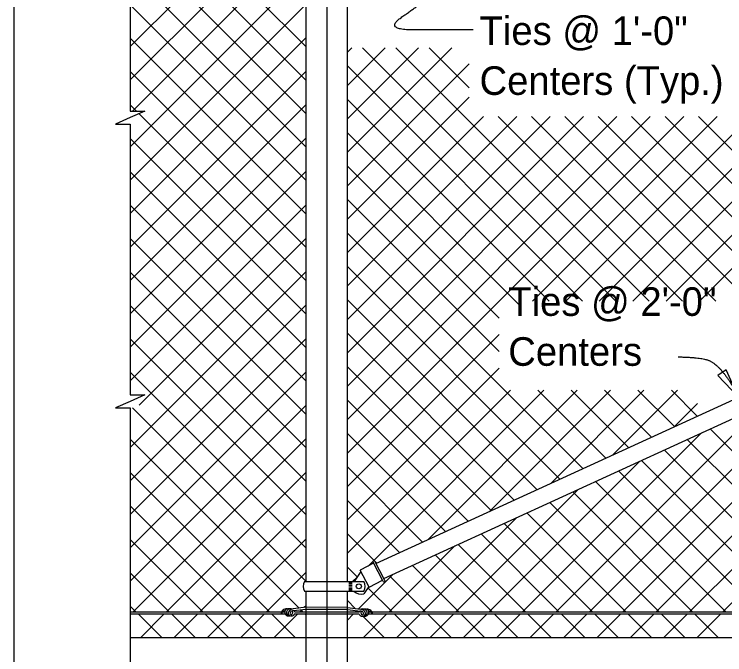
# Model space of a CAD drawing. Extents: x 0 to 41.1, y 0 to 26.4.
# Drawn here: x 0 to 5.02, y 17.35 to 21.87 of the extents above; entities that cross this region are included whole.
import ezdxf

# ---------------------------------------------------------------- set-up
doc = ezdxf.new("R2010")
doc.units = 0
for name, color, linetype in [('CL_Major', 7, 'Continuous'), ('Dimension', 7, 'Continuous'), ('Miscellaneous', 7, 'Continuous'), ('Miscellaneous1', 7, 'Continuous'), ('SteelMisc', 7, 'Continuous'), ('SteelMisc_h', 7, 'Continuous'), ('SupstrConc', 7, 'Continuous'), ('TextStructures', 7, 'Continuous')]:
    doc.layers.add(name, color=color, linetype=linetype)

msp = doc.modelspace()

# ---------------------------------------------------------------- linework, layer by layer
at = {"layer": 'CL_Major'}
msp.add_line((2.2062, 25.6784), (2.2062, 14.8533), dxfattribs=at)
at = {"layer": 'Dimension'}
for points in [[(0.8194, 24.349), (0.8194, 21.1819), (0.9227, 21.1819), (0.8194, 21.1369), (0.716, 21.0919), (0.8194, 21.0919), (0.8194, 20.1983)], [(0.8194, 20.1983), (0.8194, 19.1806), (0.9227, 19.1806), (0.8194, 19.1356), (0.716, 19.0906), (0.8194, 19.0906), (0.8194, 16.8862)]]:
    msp.add_lwpolyline(points, dxfattribs=at)
msp.add_lwpolyline([(5.1135, 19.1655), (5.0266, 19.358), (4.968, 19.3186)], close=True, dxfattribs=at)
for points in [[(3.2402, 21.7554), (3.0279, 21.7554), (2.6079, 21.7554), (2.8581, 21.9325), (2.9953, 22.0352), (2.7847, 22.0777), (2.352, 22.06)], [(4.6876, 19.4494), (4.8459, 19.4462), (4.9517, 19.4061), (5.0648, 19.263), (5.1136, 19.1655)]]:
    msp.add_open_spline(points, degree=2, dxfattribs=at)
at = {"layer": 'Miscellaneous'}
for p, q in [((1.8028, 22.3863), (0.8192, 21.4028)), ((1.567, 22.3862), (0.8192, 21.6385)), ((2.0603, 21.1639), (0.8381, 22.3861)), ((2.0603, 21.3996), (1.0738, 22.3862)), ((2.0603, 21.6353), (1.3094, 22.3862)), ((6.6782, 22.39), (4.1304, 19.8423)), ((6.9139, 22.39), (4.3661, 19.8423)), ((7.1496, 22.39), (4.6018, 19.8423)), ((7.3853, 22.39), (4.8375, 19.8423)), ((2.0163, 22.3642), (0.8341, 21.1819)), ((2.0603, 22.1725), (0.8192, 20.9314)), ((2.0603, 20.9282), (0.8192, 22.1693)), ((2.0603, 21.9368), (0.8192, 20.6957)), ((2.0603, 20.6925), (0.8192, 21.9336)), ((2.0603, 21.701), (0.8192, 20.46)), ((2.0603, 20.4568), (0.8192, 21.6979)), ((2.6187, 21.6304), (2.352, 21.3636)), ((2.383, 21.6304), (2.352, 21.5993)), ((2.8544, 21.6304), (2.352, 21.1279)), ((3.0901, 21.6304), (2.352, 20.8922)), ((4.2468, 19.8423), (2.4587, 21.6304)), ((4.4825, 19.8423), (2.6944, 21.6304)), ((3.2122, 21.3482), (2.9301, 21.6304)), ((3.2122, 21.5167), (2.352, 20.6565)), ((4.011, 19.8423), (2.352, 21.5013)), ((2.0603, 21.4653), (0.8192, 20.2243)), ((2.0603, 20.2211), (0.8192, 21.4622)), ((3.2122, 21.281), (2.352, 20.4208)), ((2.0603, 21.2296), (0.8192, 19.9886)), ((0.8638, 21.1819), (0.8192, 21.2265)), ((3.7753, 19.8423), (2.352, 21.2656)), ((2.0603, 19.9854), (0.8817, 21.164)), ((4.2544, 21.1447), (2.352, 19.2423)), ((3.783, 21.1447), (2.352, 19.7137)), ((3.3116, 21.1447), (2.352, 20.1851)), ((3.5473, 21.1447), (2.352, 19.9494)), ((4.0187, 21.1447), (2.352, 19.478)), ((4.4901, 21.1447), (2.352, 19.0066)), ((4.7182, 19.8423), (3.4157, 21.1447)), ((4.7258, 21.1447), (3.4233, 19.8423)), ((4.9539, 19.8423), (3.6514, 21.1447)), ((4.9615, 21.1447), (3.659, 19.8423)), ((5.1896, 19.8423), (3.8871, 21.1447)), ((5.1972, 21.1447), (3.8947, 19.8423)), ((5.4253, 19.8423), (4.1228, 21.1447)), ((5.9529, 19.5503), (4.3585, 21.1447)), ((6.1145, 19.6244), (4.5942, 21.1447)), ((6.2762, 19.6985), (4.8299, 21.1447)), ((3.5642, 19.8177), (2.352, 21.0299)), ((2.0603, 20.9939), (0.8192, 19.7529)), ((2.0603, 19.7497), (0.8192, 20.9908)), ((3.4233, 19.7229), (2.352, 20.7942)), ((2.0603, 20.7582), (0.8192, 19.5171)), ((2.0603, 19.514), (0.8192, 20.7551)), ((2.0603, 20.5225), (0.8192, 19.2814)), ((2.0603, 19.2783), (0.8192, 20.5194)), ((3.4233, 19.4872), (2.352, 20.5585)), ((4.0136, 18.6612), (2.352, 20.3228)), ((2.0603, 19.0426), (0.8192, 20.2837)), ((2.0603, 20.2868), (0.8817, 19.1083)), ((3.852, 18.5871), (2.352, 20.0871)), ((7.463, 20.1106), (5.0009, 17.6486)), ((2.0603, 20.0511), (0.8192, 18.81)), ((2.0603, 18.8069), (0.8192, 20.048)), ((7.0277, 19.9111), (4.7652, 17.6486)), ((2.0603, 19.8154), (0.8192, 18.5743)), ((3.6903, 18.513), (2.352, 19.8514)), ((3.4233, 19.8423), (2.352, 18.7709)), ((2.0603, 18.5712), (0.8192, 19.8123)), ((6.5925, 19.7116), (4.5295, 17.6486)), ((3.5287, 18.439), (2.352, 19.6157)), ((2.0603, 19.5797), (0.8192, 18.3386)), ((2.0603, 18.3355), (0.8192, 19.5766)), ((3.4233, 19.6066), (2.352, 18.5352)), ((6.1573, 19.5121), (4.2938, 17.6486)), ((3.3671, 18.3649), (2.352, 19.38)), ((3.4233, 19.3709), (2.352, 18.2995)), ((2.0603, 19.344), (0.8192, 18.1029)), ((2.0603, 18.0998), (0.8192, 19.3409)), ((5.7221, 19.3126), (4.0581, 17.6486)), ((3.5027, 19.2146), (2.352, 18.0638)), ((3.7384, 19.2146), (2.4979, 17.974)), ((3.9741, 19.2146), (2.919, 18.1595)), ((4.2098, 19.2146), (3.3543, 18.359)), ((4.1752, 18.7353), (3.6959, 19.2146)), ((4.4455, 19.2146), (3.7895, 18.5585)), ((4.3368, 18.8094), (3.9317, 19.2146)), ((4.4984, 18.8835), (4.1674, 19.2146)), ((4.6812, 19.2146), (4.2247, 18.758)), ((4.66, 18.9576), (4.4031, 19.2146)), ((4.8216, 19.0317), (4.6388, 19.2146)), ((3.2055, 18.2908), (2.352, 19.1443)), ((5.2869, 19.1131), (3.8224, 17.6486)), ((4.8227, 19.1203), (4.6599, 18.9575)), ((2.0603, 19.1083), (0.8192, 17.8672)), ((2.0603, 17.8641), (0.8339, 19.0905)), ((4.8517, 18.9136), (3.5867, 17.6486)), ((6.2048, 17.6486), (4.912, 18.9413)), ((2.012, 17.6767), (0.8192, 18.8695)), ((2.0603, 18.8726), (0.8363, 17.6486)), ((3.0439, 18.2167), (2.352, 18.9086)), ((5.9691, 17.6486), (4.7504, 18.8672)), ((5.7333, 17.6486), (4.5888, 18.7931)), ((4.4165, 18.7141), (3.3509, 17.6486)), ((5.4976, 17.6486), (4.4272, 18.719)), ((2.8823, 18.1426), (2.352, 18.6729)), ((1.8044, 17.6486), (0.8192, 18.6338)), ((2.0603, 18.6369), (1.072, 17.6486)), ((5.2619, 17.6486), (4.2656, 18.6449)), ((5.0262, 17.6486), (4.104, 18.5708)), ((3.9813, 18.5146), (3.1152, 17.6486)), ((4.7905, 17.6486), (3.9424, 18.4967)), ((2.7207, 18.0685), (2.352, 18.4372)), ((4.5548, 17.6486), (3.7807, 18.4227)), ((1.5687, 17.6486), (0.8192, 18.3981)), ((2.0603, 18.4012), (1.3077, 17.6486)), ((3.5461, 18.3151), (2.8795, 17.6486)), ((4.3191, 17.6486), (3.6191, 18.3486)), ((4.0834, 17.6486), (3.4575, 18.2745)), ((1.333, 17.6486), (0.8192, 18.1624)), ((2.0603, 18.1655), (1.5434, 17.6486)), ((2.5591, 17.9944), (2.352, 18.2015)), ((3.8477, 17.6486), (3.2959, 18.2004)), ((3.1108, 18.1156), (2.6438, 17.6486)), ((3.612, 17.6486), (3.1343, 18.1263)), ((3.3763, 17.6486), (2.9727, 18.0522)), ((2.4208, 17.897), (2.352, 17.9658)), ((3.1406, 17.6486), (2.8111, 17.9781)), ((1.0973, 17.6486), (0.8192, 17.9267)), ((2.0603, 17.9298), (1.7791, 17.6486)), ((2.6756, 17.9161), (2.4309, 17.6713)), ((2.4207, 17.8968), (2.3885, 17.8646)), ((2.9049, 17.6486), (2.6494, 17.904)), ((2.6692, 17.6486), (2.4966, 17.8212)), ((2.4079, 17.6742), (2.352, 17.7301)), ((0.8616, 17.6486), (0.8192, 17.691)), ((2.0315, 17.6653), (2.0148, 17.6486)), ((2.0401, 17.6486), (2.0242, 17.6645)), ((2.0603, 17.6941), (2.0474, 17.6812)), ((2.4193, 17.6597), (2.4081, 17.6486)), ((2.4335, 17.6486), (2.4228, 17.6593)), ((0.8215, 17.6338), (0.8192, 17.6315)), ((1.0409, 17.4693), (0.8764, 17.6338)), ((1.0572, 17.6338), (0.8927, 17.4693)), ((1.2766, 17.4693), (1.1121, 17.6338)), ((1.2929, 17.6338), (1.1284, 17.4693)), ((1.5123, 17.4693), (1.3478, 17.6338)), ((1.5286, 17.6338), (1.3641, 17.4693)), ((1.748, 17.4693), (1.5835, 17.6338)), ((1.7643, 17.6338), (1.5998, 17.4693)), ((1.9837, 17.4693), (1.8192, 17.6338)), ((2, 17.6338), (1.8355, 17.4693)), ((2.0603, 17.6284), (2.0549, 17.6338)), ((2.3934, 17.6338), (2.352, 17.5924)), ((2.6127, 17.4693), (2.4617, 17.6203)), ((2.6291, 17.6338), (2.4646, 17.4693)), ((2.8484, 17.4693), (2.684, 17.6338)), ((2.8648, 17.6338), (2.7003, 17.4693)), ((3.0842, 17.4693), (2.9197, 17.6338)), ((3.1005, 17.6338), (2.936, 17.4693)), ((3.3199, 17.4693), (3.1554, 17.6338)), ((3.3362, 17.6338), (3.1717, 17.4693)), ((3.5556, 17.4693), (3.3911, 17.6338)), ((3.5719, 17.6338), (3.4074, 17.4693)), ((3.7913, 17.4693), (3.6268, 17.6338)), ((3.8076, 17.6338), (3.6431, 17.4693)), ((4.027, 17.4693), (3.8625, 17.6338)), ((4.0433, 17.6338), (3.8788, 17.4693)), ((4.2627, 17.4693), (4.0982, 17.6338)), ((4.279, 17.6338), (4.1145, 17.4693)), ((4.4984, 17.4693), (4.3339, 17.6338)), ((4.5147, 17.6338), (4.3502, 17.4693)), ((4.7341, 17.4693), (4.5696, 17.6338)), ((4.7504, 17.6338), (4.5859, 17.4693)), ((4.9698, 17.4693), (4.8053, 17.6338)), ((4.9861, 17.6338), (4.8216, 17.4693))]:
    msp.add_line(p, q, dxfattribs=at)
at = {"layer": 'Miscellaneous1'}
msp.add_lwpolyline([(0, 26.4), (41.0667, 26.4), (41.0667, 0), (0, 0)], close=True, dxfattribs=at)
at = {"layer": 'SteelMisc'}
for p, q in [((2.0603, 17.8646), (2.0603, 24.349)), ((2.352, 17.8646), (2.352, 24.349)), ((2.5526, 17.9915), (11.8021, 22.2317)), ((2.6096, 17.8858), (11.8582, 22.1255)), ((2.6171, 17.8717), (2.5446, 18.0088)), ((2.5369, 17.9947), (2.4426, 17.9448)), ((2.6052, 17.8654), (2.5328, 18.0026)), ((2.4468, 17.9368), (2.3999, 17.8651)), ((2.5063, 17.8242), (2.4426, 17.9448)), ((2.049, 17.8646), (2.4687, 17.8646)), ((2.3864, 17.8584), (2.3629, 17.8584)), ((2.5063, 17.8242), (2.6006, 17.8741)), ((2.3864, 17.8486), (2.3629, 17.8486)), ((2.3864, 17.8368), (2.3629, 17.8368)), ((2.3864, 17.825), (2.3629, 17.825)), ((2.3864, 17.8142), (2.3629, 17.8142)), ((2.5029, 17.8308), (2.4681, 17.7777)), ((2.0491, 17.7968), (2.4687, 17.7968)), ((2.0603, 17.0944), (2.0603, 17.7968)), ((2.352, 17.0944), (2.352, 17.7968)), ((2.3864, 17.8046), (2.3629, 17.8046)), ((2.0608, 17.6829), (1.9689, 17.6713)), ((2.0608, 17.6683), (1.9689, 17.6588)), ((2.352, 17.6812), (2.0608, 17.6829)), ((2.352, 17.6667), (2.0608, 17.6683)), ((2.352, 17.6812), (2.4449, 17.6695)), ((2.352, 17.6667), (2.4448, 17.657)), ((1.8859, 17.6486), (0.8192, 17.6486)), ((1.9145, 17.6338), (0.8192, 17.6338)), ((1.9096, 17.6486), (1.8943, 17.6486)), ((2.0603, 17.6338), (1.9773, 17.6338)), ((2.0603, 17.6486), (1.9799, 17.6486)), ((2.4342, 17.6486), (2.352, 17.6486)), ((2.4356, 17.6338), (2.352, 17.6338)), ((11.8982, 17.6338), (2.5005, 17.6338)), ((2.5172, 17.6486), (2.5041, 17.6486)), ((11.8969, 17.6486), (2.5271, 17.6486))]:
    msp.add_line(p, q, dxfattribs=at)
for centre, start, end in [((2.5385, 18.0058), 27.851, 207.851), ((2.611, 17.8686), 207.851, 27.851)]:
    msp.add_arc(centre, 0.00673, start, end, dxfattribs=at)
for centre, major_axis, ratio, start_param, end_param in [((2.1181, 17.8309), (-0.0776, 0), 0.957868, 5.811591, 6.758603), ((2.3995, 17.8309), (0.0776, 0), 0.957868, 5.810211, 6.75616), ((2.4515, 17.846), (-0.0647, -0.0342), 0.957868, 0.271397, 1.331255), ((1.9209, 17.6361), (0.0373, 0), 0.957868, 1.427863, 3.108042), ((1.942, 17.5964), (-0.0724, 0), 0.957868, 5.133134, 5.652106), ((1.9345, 17.648), (-0.0249, 0), 0.957868, 5.913851, 7.104804), ((1.9333, 17.6505), (0.023, 0), 0.957868, 1.234085, 2.861055), ((1.9521, 17.6452), (0.0295, 0), 0.957868, 1.132635, 3.996184), ((1.9656, 17.647), (-0.0303, -0.0108), 0.724765, 4.35367, 6.224248), ((1.9706, 17.634), (-0.0259, 0), 0.957868, 4.777514, 5.646371), ((1.9549, 17.6463), (0.0119, 0), 0.957868, 5.725876, 7.416677), ((1.9551, 17.6451), (0.0251, 0), 0.957868, 0.146361, 0.642491), ((2.4586, 17.6433), (-0.0251, 0), 0.957868, 5.640601, 6.061443), ((2.4431, 17.6323), (0.0259, 0), 0.957868, 0.636815, 1.505671), ((2.4482, 17.6452), (0.0303, -0.0108), 0.724765, 0.058937, 1.929515), ((2.4617, 17.6434), (-0.0295, 0), 0.957868, 2.287002, 5.15055), ((2.4804, 17.6488), (-0.023, 0), 0.957868, 3.422131, 5.0491), ((2.4929, 17.6343), (-0.0373, 0), 0.957868, 3.175144, 4.855322), ((2.4718, 17.5946), (0.0724, 0), 0.957868, 0.631079, 1.150052), ((1.9359, 17.644), (0.0231, 0), 0.957868, 3.795406, 4.839145), ((1.942, 17.6383), (0.0206, -0.0021), 0.798607, 4.329004, 5.170153), ((1.9554, 17.6383), (0.0206, -0.0021), 0.798607, 3.319435, 5.221193), ((1.9623, 17.6429), (-0.0139, 0), 0.957868, 5.822914, 6.905413), ((1.9566, 17.6405), (-0.00795, 0), 0.957868, 0.785393, 2.999691), ((1.9481, 17.6571), (0.0391, 0), 0.957868, 5.134108, 5.414681), ((1.9549, 17.6463), (0.0119, 0), 0.957868, 5.639684, 5.723117), ((1.9551, 17.6451), (0.0251, 0), 0.957868, 5.523427, 5.795636), ((2.4586, 17.6433), (-0.0251, 0), 0.957868, 0.405384, 0.751829), ((2.4657, 17.6553), (-0.0391, 0), 0.957868, 0.863445, 1.149077), ((2.4589, 17.6445), (-0.0119, 0), 0.957868, 5.149694, 6.840495), ((2.4589, 17.6445), (-0.0119, 0), 0.957868, 0.560069, 0.643501), ((2.4572, 17.6387), (0.00795, 0), 0.957868, 3.283493, 6.243757), ((2.4583, 17.6366), (-0.0206, -0.0021), 0.798607, 1.063032, 2.96375), ((2.4515, 17.6411), (0.0139, 0), 0.957868, 6.080589, 6.743456), ((2.4718, 17.6366), (-0.0206, -0.0021), 0.798607, 1.113032, 1.956656), ((2.4779, 17.6423), (-0.0231, 0), 0.957868, 1.44404, 2.503632), ((2.4793, 17.6463), (0.0249, 0), 0.957868, 5.476514, 6.65252)]:
    msp.add_ellipse(centre, major_axis=major_axis, ratio=ratio, start_param=start_param, end_param=end_param, dxfattribs=at)
msp.add_ellipse((2.4328, 17.8313), major_axis=(-0.0178, 0), ratio=0.957868, dxfattribs=at)
at = {"layer": 'SteelMisc_h'}
for p, q in [((2.352, 17.6486), (2.0603, 17.6486)), ((2.352, 17.6338), (2.0603, 17.6338))]:
    msp.add_line(p, q, dxfattribs=at)
at = {"layer": 'SupstrConc'}
msp.add_line((0.8193, 17.4693), (5.3495, 17.4693), dxfattribs=at)

# ---------------------------------------------------------------- texts
at = {"layer": 'TextStructures'}
for s, p in [('Ties @ 1\'-0" ', (3.285, 21.6493)), ('Centers (Typ.)', (3.285, 21.2973)), ('Ties @ 2\'-0" ', (3.4877, 19.7385)), ('Centers', (3.4877, 19.3865))]:
    msp.add_text(s, height=0.2016, dxfattribs=at).set_placement(p)

doc.saveas('drawing.dxf')
